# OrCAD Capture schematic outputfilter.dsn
size A; title: Buck-Boost Converter; rev: 1
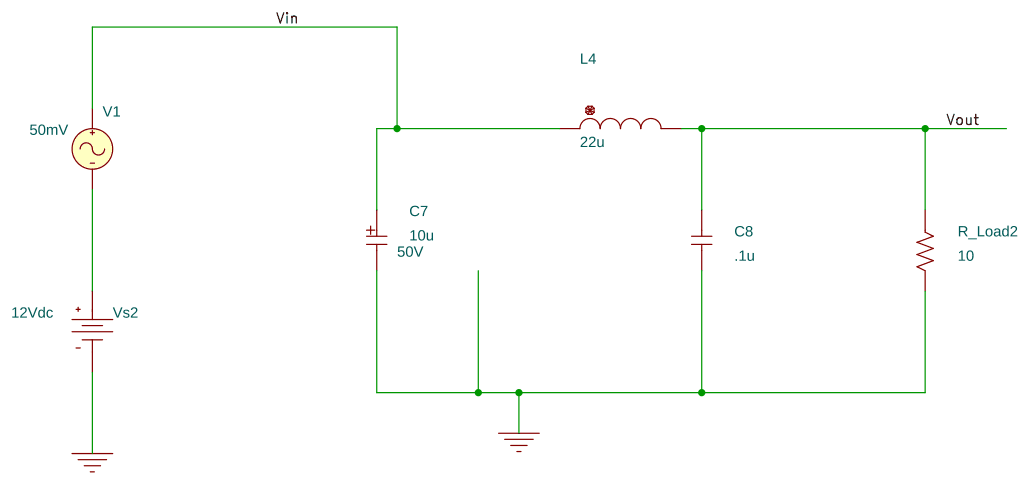
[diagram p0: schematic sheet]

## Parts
C7  10u  [CPAX575x150031]
C8  .1u  [RAD/CK05]
L4  22u  [DISC/.350x.175/LS.200x.100/.034]
R_Load2  10  [AX/RC05]
V1  VAC
Vs2  VDC

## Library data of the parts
C7 = C_elect: Voltage: 50V
C8 = C: IC: 70
L4 = L
R_Load2 = R
V1 = VAC: ACMAG: 50mV
Vs2 = VDC: DC: 12Vdc

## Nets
Vin: C7.P(+) L4.1 V1.1(+)
0: C7.N(-) C8.2 R_Load2.2 Vs2.1(-)
Vout: C8.1 L4.2 R_Load2.1
N9036580: V1.2(-) Vs2.0(+)
